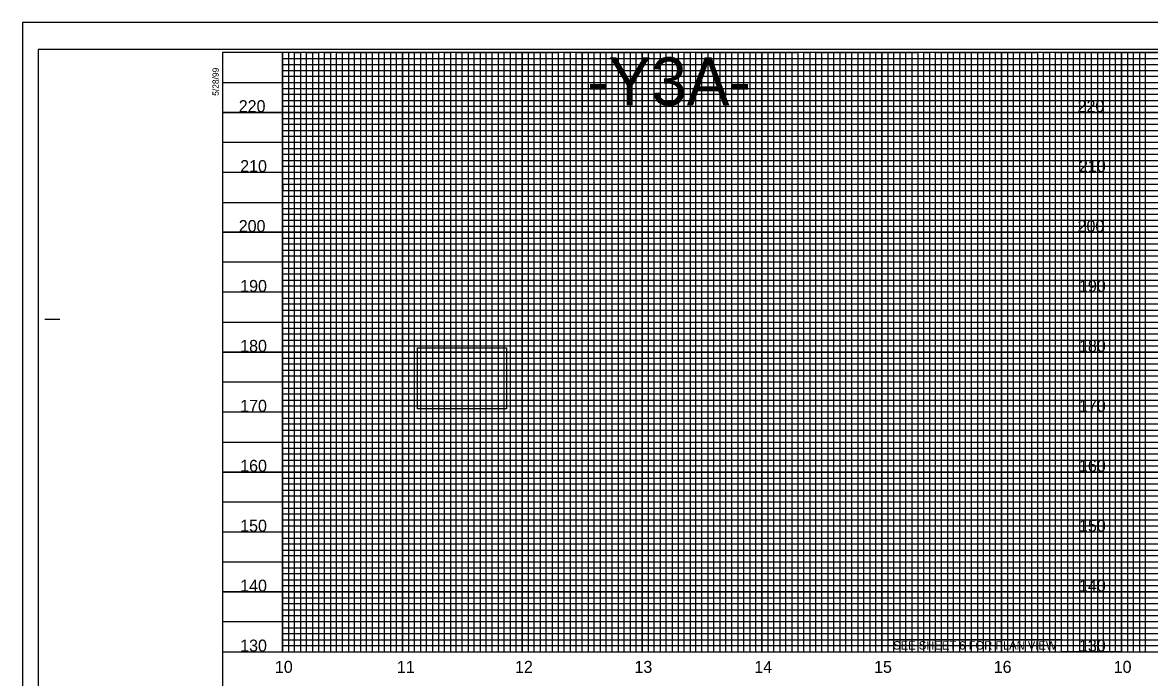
# Model space of a CAD drawing. Extents: x 1779926 to 1781626, y 618464 to 619564.
# Drawn here: x 1779926 to 1780866, y 619018 to 619564 of the extents above; entities that cross this region are included whole.
import ezdxf

# ---------------------------------------------------------------- set-up
doc = ezdxf.new("R2010")
doc.units = 0
for name, color, linetype in [('Exist Vertical Profile Horizontal Axis Label Major', 7, 'Continuous'), ('Exist Vertical Profile Vertical Axis Label', 7, 'Continuous'), ('Prop DSN Text', 7, 'Continuous'), ('Prop Grid Mask', 7, 'Continuous'), ('Sheet DOT Grid CELL', 7, 'Continuous'), ('Sheet Layout Profile Border Port 1', 7, 'Continuous'), ('Sheet Plot Border Inside CELL', 7, 'Continuous'), ('Sheet Plot Border Outside CELL', 7, 'Continuous'), ('Sheet Profile CELL', 7, 'Continuous'), ('Sheet Profile Grid Major CELL', 7, 'Continuous'), ('Sheet Profile Grid Middle CELL', 7, 'Continuous'), ('Sheet Profile Grid Minor CELL', 7, 'Continuous')]:
    doc.layers.add(name, color=color, linetype=linetype)

msp = doc.modelspace()

# ---------------------------------------------------------------- linework, layer by layer
at = {"layer": 'Prop Grid Mask'}
for points in [[(1780548.07, 619539.19), (1780392.96, 619539.19), (1780392.96, 619489.19), (1780548.07, 619489.19)], [(1780792.96, 619539.19), (1780842.96, 619539.19), (1780842.96, 619039.19), (1780792.96, 619039.19)], [(1780255.48, 619292.88), (1780329.73, 619292.88), (1780329.73, 619241.97), (1780255.48, 619241.97)], [(1780792.96, 619049.19), (1780647.96, 619049.19), (1780647.96, 619039.19), (1780792.96, 619039.19)]]:
    msp.add_lwpolyline(points, close=True, dxfattribs=at)
at = {"layer": 'Sheet DOT Grid CELL'}
for p, q in [((1780142.96, 619039.19), (1780142.96, 619539.19)), ((1780192.96, 619039.19), (1780192.96, 619539.19)), ((1780242.96, 619039.19), (1780242.96, 619539.19)), ((1780292.96, 619039.19), (1780292.96, 619539.19)), ((1780342.96, 619039.19), (1780342.96, 619539.19)), ((1780392.96, 619039.19), (1780392.96, 619539.19)), ((1780442.96, 619039.19), (1780442.96, 619539.19)), ((1780492.96, 619039.19), (1780492.96, 619539.19)), ((1780542.96, 619039.19), (1780542.96, 619539.19)), ((1780592.96, 619039.19), (1780592.96, 619539.19)), ((1780642.96, 619039.19), (1780642.96, 619539.19)), ((1780692.96, 619039.19), (1780692.96, 619539.19)), ((1780742.96, 619039.19), (1780742.96, 619539.19)), ((1780792.96, 619039.19), (1780792.96, 619539.19)), ((1780842.96, 619039.19), (1780842.96, 619539.19)), ((1781392.91, 619489.19), (1780092.96, 619489.19)), ((1781392.91, 619439.19), (1780092.96, 619439.19)), ((1781392.96, 619389.19), (1780092.96, 619389.19)), ((1781392.91, 619339.19), (1780092.96, 619339.19)), ((1781592.96, 619289.19), (1780092.96, 619289.19)), ((1781592.96, 619239.19), (1780092.96, 619239.19)), ((1781592.96, 619189.19), (1780092.96, 619189.19)), ((1781592.96, 619139.19), (1780092.96, 619139.19)), ((1781592.96, 619089.19), (1780092.96, 619089.19))]:
    msp.add_line(p, q, dxfattribs=at)
at = {"layer": 'Sheet Layout Profile Border Port 1'}
for points in [[(1781542.96, 619099.19), (1781542.96, 619314.19), (1781392.91, 619314.19), (1781392.96, 619539.19), (1780142.96, 619539.19), (1780142.96, 619039.19), (1781542.96, 619039.19), (1781542.96, 619049.19)], [(1780142.96, 619378.14), (1780142.96, 619039.19), (1781542.96, 619039.19), (1781542.96, 619314.19)]]:
    msp.add_lwpolyline(points, dxfattribs=at)
at = {"layer": 'Sheet Plot Border Inside CELL'}
msp.add_lwpolyline([(1779938.96, 618486.64), (1781605.46, 618486.64), (1781605.46, 619541.74), (1779938.96, 619541.74)], close=True, dxfattribs=at)
at = {"layer": 'Sheet Plot Border Outside CELL'}
msp.add_lwpolyline([(1779925.96, 618464.19), (1781625.96, 618464.19), (1781625.96, 619564.19), (1779925.96, 619564.19)], close=True, dxfattribs=at)
at = {"layer": 'Sheet Profile CELL'}
for p, q in [((1779944.46, 619316.69), (1779956.96, 619316.69)), ((1780092.96, 619039.19), (1781592.96, 619039.19))]:
    msp.add_line(p, q, dxfattribs=at)
msp.add_lwpolyline([(1781592.96, 619539.19), (1780092.96, 619539.19), (1780092.96, 618489.19), (1781592.96, 618489.19)], close=True, dxfattribs=at)
at = {"layer": 'Sheet Profile Grid Major CELL'}
for points in [[(1780142.96, 619539.19), (1780142.96, 619039.19), (1780192.96, 619039.19), (1780192.96, 619539.19), (1780242.96, 619539.19), (1780242.96, 619039.19), (1780292.96, 619039.19), (1780292.96, 619539.19), (1780342.96, 619539.19), (1780342.96, 619039.19), (1780392.96, 619039.19), (1780392.96, 619539.19), (1780442.96, 619539.19), (1780442.96, 619039.19), (1780492.96, 619039.19), (1780492.96, 619539.19), (1780542.96, 619539.19), (1780542.96, 619039.19), (1780592.96, 619039.19), (1780592.96, 619539.19), (1780642.96, 619539.19), (1780642.96, 619039.19), (1780692.96, 619039.19), (1780692.96, 619539.19), (1780742.96, 619539.19), (1780742.96, 619039.19), (1780792.96, 619039.19), (1780792.96, 619539.19), (1780842.96, 619539.19), (1780842.96, 619039.19), (1780892.96, 619039.19)], [(1780092.96, 619489.19), (1781392.96, 619489.19)], [(1781392.96, 619439.19), (1780092.96, 619439.19), (1780092.96, 619389.19), (1781392.96, 619389.19)], [(1781392.96, 619339.19), (1780092.96, 619339.19), (1780092.96, 619289.19), (1781592.96, 619289.19)], [(1781592.96, 619239.19), (1780092.96, 619239.19), (1780092.96, 619189.19), (1781592.96, 619189.19)], [(1781592.96, 619139.19), (1780092.96, 619139.19), (1780092.96, 619139.19), (1780092.96, 619089.19), (1781592.96, 619089.19)]]:
    msp.add_lwpolyline(points, dxfattribs=at)
at = {"layer": 'Sheet Profile Grid Middle CELL'}
msp.add_line((1780092.96, 619514.19), (1781392.91, 619514.19), dxfattribs=at)
for points in [[(1780167.96, 619539.19), (1780167.96, 619039.19), (1780217.96, 619039.19), (1780217.96, 619539.19), (1780267.96, 619539.19), (1780267.96, 619039.19), (1780317.96, 619039.19), (1780317.96, 619539.19), (1780367.96, 619539.19), (1780367.96, 619039.19), (1780417.96, 619039.19), (1780417.96, 619539.19), (1780467.96, 619539.19), (1780467.96, 619039.19), (1780517.96, 619039.19), (1780517.96, 619539.19), (1780567.96, 619539.19), (1780567.96, 619039.19), (1780617.96, 619039.19), (1780617.96, 619539.19), (1780667.96, 619539.19), (1780667.96, 619039.19), (1780717.96, 619039.19), (1780717.96, 619039.19), (1780717.96, 619539.19), (1780767.96, 619539.19), (1780767.96, 619039.19), (1780817.96, 619039.19), (1780817.96, 619539.19), (1780867.96, 619539.19)], [(1781392.96, 619464.19), (1780092.96, 619464.19), (1780092.96, 619414.19), (1781392.96, 619414.19)], [(1781392.91, 619364.19), (1780092.96, 619364.19), (1780092.96, 619314.19), (1781417.96, 619314.19)], [(1781592.96, 619264.19), (1780092.96, 619264.19), (1780092.96, 619214.19), (1781592.96, 619214.19)], [(1781592.96, 619164.19), (1780092.96, 619164.19), (1780092.96, 619114.19), (1781592.96, 619114.19)], [(1781592.96, 619064.19), (1780092.96, 619064.19)]]:
    msp.add_lwpolyline(points, dxfattribs=at)
at = {"layer": 'Sheet Profile Grid Minor CELL'}
for p, q in [((1780142.96, 619534.19), (1781392.96, 619534.19)), ((1780142.96, 619529.19), (1780142.96, 619529.19)), ((1781392.96, 619529.19), (1780142.96, 619528.84)), ((1780142.96, 619524.19), (1781392.96, 619524.19)), ((1781392.91, 619404.19), (1780142.96, 619404.19)), ((1781392.96, 619399.19), (1780142.96, 619399.19)), ((1781392.96, 619394.19), (1780142.96, 619394.19)), ((1780142.96, 619384.19), (1781392.96, 619384.19)), ((1781392.96, 619379.19), (1780142.96, 619379.19)), ((1780142.96, 619374.19), (1781392.91, 619374.19)), ((1781392.91, 619354.19), (1780142.96, 619354.19)), ((1780142.96, 619349.19), (1781392.91, 619349.19)), ((1781392.91, 619329.19), (1780142.96, 619329.19)), ((1780142.96, 619324.19), (1781392.91, 619324.19)), ((1781542.96, 619304.19), (1780142.96, 619304.19)), ((1780142.96, 619299.19), (1781542.96, 619299.19)), ((1781542.96, 619294.19), (1780142.96, 619294.19)), ((1780142.96, 619284.19), (1781542.96, 619284.19)), ((1781542.96, 619279.19), (1780142.96, 619279.19)), ((1780142.96, 619274.19), (1781542.96, 619274.19)), ((1781542.96, 619269.19), (1780142.96, 619269.19)), ((1780142.96, 619259.19), (1781542.96, 619259.19)), ((1781542.96, 619254.19), (1780142.96, 619254.19)), ((1780142.96, 619249.19), (1781542.96, 619249.19)), ((1781542.96, 619244.19), (1780142.96, 619244.19)), ((1780142.96, 619234.19), (1781542.96, 619234.19)), ((1781542.96, 619229.19), (1780142.96, 619229.19)), ((1780142.96, 619224.19), (1781542.96, 619224.19)), ((1781542.96, 619219.19), (1780142.96, 619219.19)), ((1780142.96, 619209.19), (1781542.96, 619209.19)), ((1781542.96, 619204.19), (1780142.96, 619204.19)), ((1780142.96, 619199.19), (1781542.96, 619199.19)), ((1781542.96, 619194.19), (1780142.96, 619194.19)), ((1780142.96, 619184.19), (1781542.96, 619184.19)), ((1781542.96, 619179.19), (1780142.96, 619179.19)), ((1780142.96, 619174.19), (1781542.96, 619174.19)), ((1781542.96, 619169.19), (1780142.96, 619169.19)), ((1780142.96, 619159.19), (1781542.96, 619159.19)), ((1781542.96, 619154.19), (1780142.96, 619154.19)), ((1781542.96, 619149.19), (1780142.96, 619149.19)), ((1781542.96, 619144.19), (1780142.96, 619144.19)), ((1780142.96, 619134.19), (1781542.96, 619134.19)), ((1781542.96, 619129.19), (1780142.96, 619129.19)), ((1780142.96, 619124.19), (1781542.96, 619124.19)), ((1781542.96, 619119.19), (1780142.96, 619119.19)), ((1780142.96, 619109.19), (1781542.96, 619109.19)), ((1781542.96, 619104.19), (1780142.96, 619104.19)), ((1780142.96, 619099.19), (1781542.96, 619099.19)), ((1781542.96, 619094.19), (1780142.96, 619094.19)), ((1780142.96, 619084.19), (1781542.96, 619084.19)), ((1781542.96, 619079.19), (1780142.96, 619079.19)), ((1780142.96, 619074.19), (1781542.96, 619074.19)), ((1781542.96, 619069.19), (1780142.96, 619069.19)), ((1780142.96, 619059.19), (1781542.96, 619059.19)), ((1781542.96, 619054.19), (1780142.96, 619054.19)), ((1780142.96, 619049.19), (1781542.96, 619049.19))]:
    msp.add_line(p, q, dxfattribs=at)
for points in [[(1780147.96, 619539.19), (1780147.96, 619039.19), (1780152.96, 619039.19), (1780152.96, 619539.19), (1780157.96, 619539.19), (1780157.96, 619039.19), (1780162.96, 619039.19), (1780162.96, 619539.19), (1780172.96, 619539.19), (1780172.96, 619039.19), (1780177.96, 619039.19), (1780177.96, 619539.19), (1780182.96, 619539.19), (1780182.96, 619039.19), (1780187.96, 619039.19), (1780197.96, 619039.19), (1780202.96, 619039.19), (1780202.96, 619539.19), (1780207.96, 619539.19), (1780207.96, 619039.19), (1780212.96, 619039.19), (1780212.96, 619539.19), (1780222.96, 619539.19), (1780222.96, 619039.19), (1780227.96, 619039.19), (1780227.96, 619539.19), (1780232.96, 619539.19), (1780232.96, 619039.19), (1780237.96, 619039.19), (1780237.96, 619539.19), (1780247.96, 619539.19), (1780247.96, 619039.19), (1780252.96, 619039.19), (1780252.96, 619539.19), (1780257.96, 619539.19), (1780257.96, 619039.19), (1780262.96, 619039.19), (1780262.96, 619539.19), (1780272.96, 619539.19), (1780272.96, 619039.19), (1780277.96, 619039.19), (1780277.96, 619539.19), (1780282.96, 619539.19), (1780282.96, 619039.19), (1780287.96, 619039.19), (1780287.96, 619539.19), (1780297.96, 619539.19), (1780297.96, 619039.19), (1780302.96, 619039.19), (1780302.96, 619539.19), (1780307.96, 619539.19), (1780307.96, 619039.19), (1780312.96, 619039.19), (1780312.96, 619539.19), (1780322.96, 619539.19), (1780322.96, 619039.19), (1780327.96, 619039.19), (1780327.96, 619539.19), (1780332.96, 619539.19), (1780332.96, 619039.19), (1780337.96, 619039.19), (1780337.96, 619539.19), (1780347.96, 619539.19), (1780347.96, 619039.19), (1780352.96, 619039.19), (1780352.96, 619539.19), (1780357.96, 619539.19), (1780357.96, 619039.19)], [(1780187.96, 619039.19), (1780187.96, 619539.19), (1780197.96, 619539.19), (1780197.96, 619039.19)], [(1780357.96, 619039.19), (1780362.96, 619039.19), (1780362.96, 619539.19), (1780372.96, 619539.19), (1780372.96, 619039.19), (1780377.96, 619039.19), (1780377.96, 619539.19), (1780382.96, 619539.19), (1780382.96, 619039.19), (1780387.96, 619039.19), (1780387.96, 619539.19), (1780397.96, 619539.19), (1780397.96, 619039.19), (1780402.96, 619039.19), (1780402.96, 619539.19), (1780407.96, 619539.19), (1780407.96, 619039.19), (1780412.96, 619039.19), (1780412.96, 619539.19), (1780422.96, 619539.19), (1780422.96, 619039.19), (1780427.96, 619039.19), (1780427.96, 619539.19), (1780432.96, 619539.19), (1780432.96, 619039.19), (1780437.96, 619039.19), (1780437.96, 619539.19), (1780447.96, 619539.19), (1780447.96, 619039.19), (1780452.96, 619039.19), (1780452.96, 619539.19), (1780457.96, 619539.19), (1780457.96, 619039.19), (1780462.96, 619039.19), (1780462.96, 619539.19), (1780472.96, 619539.19), (1780472.96, 619039.19), (1780477.96, 619039.19), (1780477.96, 619539.19), (1780482.96, 619539.19), (1780482.96, 619039.19), (1780487.96, 619039.19), (1780487.96, 619539.19), (1780497.96, 619539.19), (1780497.96, 619039.19), (1780502.96, 619039.19), (1780502.96, 619539.19), (1780507.96, 619539.19), (1780507.96, 619039.19), (1780512.96, 619039.19), (1780512.96, 619539.19), (1780522.96, 619539.19), (1780522.96, 619039.19), (1780527.96, 619039.19), (1780527.96, 619539.19), (1780532.96, 619539.19), (1780532.96, 619039.19), (1780537.96, 619039.19), (1780537.96, 619539.19), (1780547.96, 619539.19), (1780547.96, 619039.19), (1780552.96, 619039.19), (1780552.96, 619539.19), (1780557.96, 619539.19), (1780557.96, 619039.19), (1780562.96, 619039.19), (1780562.96, 619539.19), (1780572.96, 619539.19), (1780572.96, 619039.19), (1780577.96, 619039.19), (1780577.96, 619539.19), (1780582.96, 619539.19), (1780582.96, 619039.19), (1780587.96, 619039.19), (1780587.96, 619539.19), (1780597.96, 619539.19), (1780597.96, 619039.19), (1780602.96, 619039.19), (1780602.96, 619539.19), (1780607.96, 619539.19), (1780607.96, 619039.19), (1780612.96, 619039.19), (1780612.96, 619539.19), (1780622.96, 619539.19), (1780622.96, 619039.19), (1780627.96, 619039.19), (1780627.96, 619539.19), (1780632.96, 619539.19), (1780632.96, 619039.19), (1780637.96, 619039.19), (1780637.96, 619539.19), (1780647.96, 619539.19), (1780647.96, 619039.19), (1780652.96, 619039.19), (1780652.96, 619539.19), (1780657.96, 619539.19), (1780657.96, 619039.19), (1780662.96, 619039.19), (1780662.96, 619539.19), (1780672.96, 619539.19)], [(1780672.96, 619539.19), (1780672.96, 619039.19), (1780677.96, 619039.19), (1780677.96, 619539.19), (1780682.96, 619539.19), (1780682.96, 619039.19), (1780687.96, 619039.19), (1780687.96, 619539.19), (1780697.96, 619539.19), (1780697.96, 619039.19), (1780702.96, 619039.19), (1780702.96, 619539.19), (1780707.96, 619539.19), (1780707.96, 619039.19), (1780712.96, 619039.19), (1780712.96, 619539.19), (1780722.96, 619539.19), (1780722.96, 619039.19), (1780727.96, 619039.19), (1780727.96, 619539.19), (1780732.96, 619539.19), (1780732.96, 619039.19), (1780737.96, 619039.19), (1780737.96, 619539.19), (1780747.96, 619539.19), (1780747.96, 619039.19), (1780752.96, 619039.19), (1780752.96, 619539.19), (1780757.96, 619539.19), (1780757.96, 619039.19), (1780762.96, 619039.19), (1780762.96, 619539.19), (1780772.96, 619539.19), (1780772.96, 619039.19), (1780777.96, 619039.19), (1780777.96, 619539.19), (1780782.96, 619539.19), (1780782.96, 619039.19), (1780787.96, 619039.19), (1780787.96, 619539.19), (1780797.96, 619539.19), (1780797.96, 619039.19), (1780797.96, 619039.19), (1780802.96, 619039.19), (1780802.96, 619539.19), (1780807.96, 619539.19), (1780807.96, 619039.19), (1780812.96, 619039.19), (1780812.96, 619539.19), (1780822.96, 619539.19), (1780822.96, 619039.19), (1780827.96, 619039.19), (1780827.96, 619539.19), (1780832.96, 619539.19), (1780832.96, 619039.19), (1780837.96, 619039.19), (1780837.96, 619539.19), (1780847.96, 619539.19), (1780847.96, 619039.19), (1780852.96, 619039.19), (1780852.96, 619539.19), (1780857.96, 619539.19), (1780857.96, 619039.19), (1780862.96, 619039.19), (1780862.96, 619539.19), (1780872.96, 619539.19)], [(1781392.96, 619519.19), (1780142.96, 619519.19), (1780142.96, 619509.19), (1781392.96, 619509.19)], [(1781392.91, 619504.19), (1780142.96, 619504.19), (1780142.96, 619499.19), (1781392.96, 619499.19)], [(1781392.96, 619494.19), (1780142.96, 619494.19), (1780142.96, 619484.19), (1781392.96, 619484.19)], [(1781392.96, 619479.19), (1780142.96, 619479.19), (1780142.96, 619474.19), (1781392.96, 619474.19)], [(1781392.96, 619469.19), (1780142.96, 619469.19), (1780142.96, 619459.19), (1781392.96, 619459.19)], [(1781392.96, 619454.19), (1780142.96, 619454.19), (1780142.96, 619449.19), (1781392.96, 619449.19)], [(1781392.96, 619444.19), (1780142.96, 619444.19), (1780142.96, 619434.19), (1781392.96, 619434.19)], [(1781392.96, 619429.09), (1780143.06, 619429.09), (1780143.06, 619424.19), (1781392.96, 619424.19)], [(1781392.96, 619419.19), (1780142.96, 619419.19), (1780142.96, 619409.19), (1781392.96, 619409.19)], [(1781392.91, 619369.19), (1780142.96, 619369.19), (1780142.96, 619359.19), (1781392.91, 619359.19)], [(1781392.91, 619344.19), (1780142.96, 619344.19), (1780142.96, 619334.19), (1781392.91, 619334.19)], [(1781392.91, 619319.19), (1780142.96, 619319.19), (1780142.96, 619309.19), (1781542.96, 619309.19)], [(1781542.96, 619044.19), (1780142.96, 619044.19)]]:
    msp.add_lwpolyline(points, dxfattribs=at)

# ---------------------------------------------------------------- texts
at = {"layer": 'Exist Vertical Profile Horizontal Axis Label Major'}
for s, p in [('10', (1780136.54, 619021.69)), ('11', (1780238.38, 619021.69)), ('12', (1780336.93, 619021.69)), ('13', (1780436.61, 619021.69)), ('14', (1780536.66, 619021.69)), ('15', (1780636.59, 619021.69)), ('16', (1780736.42, 619021.69)), ('10', (1780836.54, 619021.69))]:
    msp.add_text(s, height=10, dxfattribs=at).set_placement(p)
at = {"layer": 'Exist Vertical Profile Vertical Axis Label'}
for s, p in [('220', (1780106.39, 619489.44)), ('220', (1780806.39, 619489.44)), ('210', (1780107.59, 619439.44)), ('210', (1780807.59, 619439.44)), ('200', (1780106.39, 619389.44)), ('200', (1780806.39, 619389.44)), ('190', (1780107.59, 619339.44)), ('190', (1780807.59, 619339.44)), ('180', (1780107.59, 619289.44)), ('180', (1780807.59, 619289.44)), ('170', (1780107.59, 619239.44)), ('170', (1780807.59, 619239.44)), ('160', (1780107.59, 619189.44)), ('160', (1780807.59, 619189.44)), ('150', (1780107.59, 619139.44)), ('150', (1780807.59, 619139.44)), ('140', (1780107.59, 619089.44)), ('140', (1780807.59, 619089.44)), ('130', (1780107.59, 619039.44)), ('130', (1780807.59, 619039.44))]:
    msp.add_text(s, height=10, dxfattribs=at).set_placement(p)
at = {"layer": 'Prop DSN Text'}
for s, height, p in [('-Y3A-', 40, (1780397.01, 619495.14)), ('SEE SHEET 6 FOR PLAN VIEW', 7, (1780652.54, 619041.14))]:
    msp.add_text(s, height=height, dxfattribs=at).set_placement(p)
at = {"layer": 'Sheet Profile CELL'}
msp.add_text('5/28/99', height=5.25, rotation=90, dxfattribs=at).set_placement((1780089.72, 619503.1))

doc.saveas('drawing.dxf')
